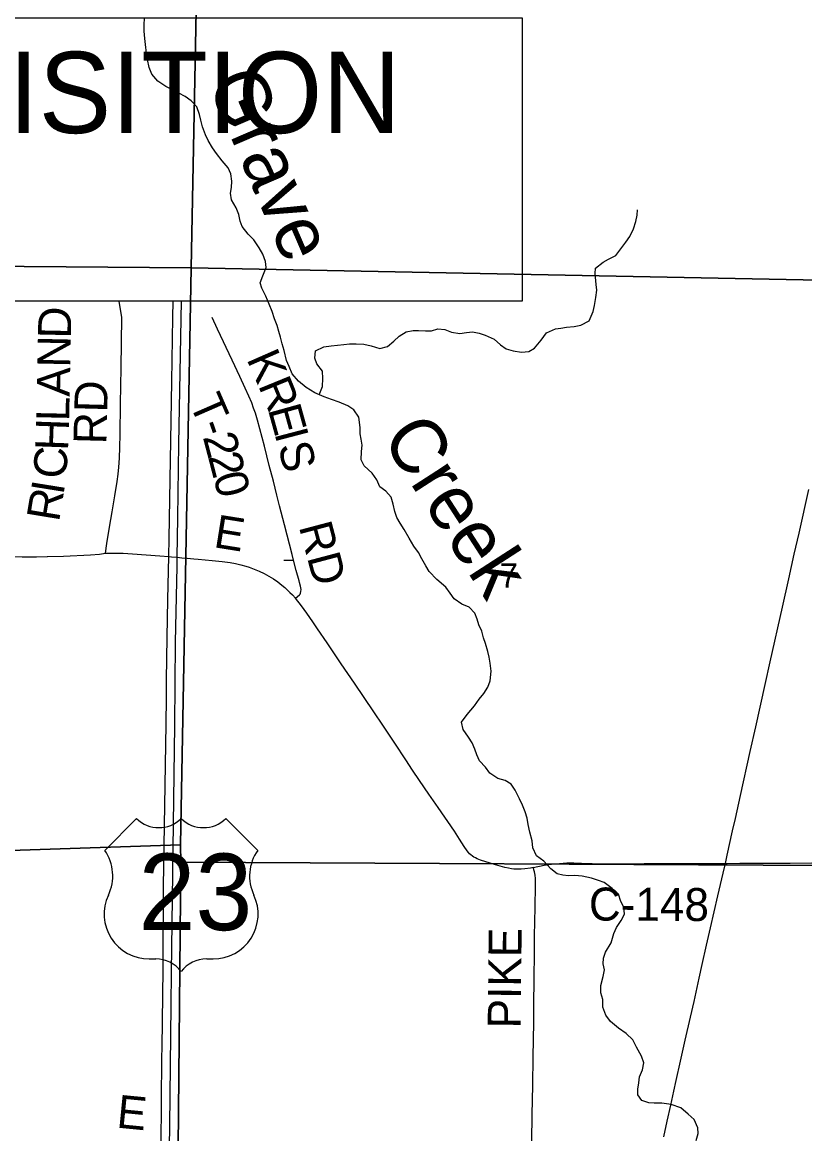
# Model space of a CAD drawing. Extents: x -97 to 34, y -21 to 22.
# Drawn here: x 8.293 to 9.642, y 14.954 to 16.869 of the extents above; entities that cross this region are included whole.
import ezdxf

# ---------------------------------------------------------------- set-up
doc = ezdxf.new("R2010")
doc.units = 0
for name, color, linetype in [('GM_X_County_Road', 7, 'Continuous'), ('GM_X_County_Road_Text', 7, 'Continuous'), ('GM_X_Minor_River', 7, 'Continuous'), ('GM_X_Minor_River_Text', 7, 'Continuous'), ('GM_X_Section', 7, 'Continuous'), ('GM_X_Section_Text', 7, 'Continuous'), ('GM_X_State_Route', 7, 'Continuous'), ('GM_X_Township_Road', 7, 'Continuous'), ('GM_X_Township_Road_Text', 7, 'Continuous'), ('GM_X_US_Location', 7, 'Continuous'), ('GM_X_US_Route', 7, 'Continuous'), ('GM_X_US_Shield', 7, 'Continuous'), ('SH_Text', 7, 'Continuous')]:
    doc.layers.add(name, color=color, linetype=linetype)

msp = doc.modelspace()

# ---------------------------------------------------------------- linework, layer by layer
at = {"layer": 'GM_X_County_Road'}
for points in [[(8.4647, 16.3607), (8.4598, 16.3891)], [(8.4365, 15.9545), (8.4388, 15.9715), (8.4434, 15.9997), (8.448, 16.0262), (8.4525, 16.0537), (8.4566, 16.0785), (8.4581, 16.0908), (8.4593, 16.1031), (8.4603, 16.1186), (8.4612, 16.1373), (8.4617, 16.159), (8.4623, 16.2119), (8.4627, 16.2431), (8.4633, 16.2742), (8.4647, 16.3607)], [(8.3356, 15.949), (8.3365, 15.949), (8.3642, 15.9495), (8.4105, 15.952), (8.4261, 15.9533), (8.4365, 15.9545)], [(8.4365, 15.9545), (8.4669, 15.9547), (8.483, 15.9538), (8.5302, 15.9504), (8.5455, 15.949), (8.5501, 15.9486)], [(7.6431, 15.9497), (7.6648, 15.9493), (7.699, 15.9492), (7.7487, 15.9488), (7.786, 15.9486), (7.814, 15.9485), (7.8668, 15.9481), (7.9134, 15.9483), (7.9507, 15.9485), (7.9849, 15.9486), (8.016, 15.9486), (8.0595, 15.9487), (8.1155, 15.9489), (8.1466, 15.9488), (8.1901, 15.9491), (8.2211, 15.9491), (8.2926, 15.9482), (8.3175, 15.9487), (8.3356, 15.949)], [(8.5501, 15.9486), (8.5597, 15.9477), (8.568, 15.947), (8.5769, 15.9462)], [(8.5769, 15.9462), (8.5888, 15.9451)], [(8.5888, 15.9451), (8.5959, 15.9445), (8.6205, 15.9421), (8.6372, 15.9404), (8.6513, 15.9384), (8.6604, 15.9368), (8.6694, 15.9349), (8.6784, 15.9325), (8.6842, 15.9307), (8.6929, 15.9274), (8.7014, 15.9238), (8.7097, 15.9197), (8.7178, 15.9152), (8.7257, 15.9104), (8.7333, 15.9051), (8.7406, 15.8995), (8.7453, 15.8955), (8.7544, 15.8871), (8.7589, 15.8828), (8.764, 15.8774)], [(8.8018, 15.8245), (8.7938, 15.8362), (8.7832, 15.8516), (8.7741, 15.8642), (8.764, 15.8774)], [(9.1738, 15.413), (9.1689, 15.4123), (9.1591, 15.411), (9.1529, 15.4104), (9.1466, 15.4101), (9.1434, 15.4102), (9.1403, 15.4104), (9.1363, 15.4108), (9.1309, 15.4118), (9.1248, 15.4133), (9.1128, 15.4167), (9.092, 15.4231), (9.0831, 15.4261), (9.0772, 15.4282), (9.0743, 15.4296), (9.0715, 15.431), (9.0689, 15.4327), (9.0662, 15.4348), (9.0639, 15.4369), (9.0619, 15.4392), (9.06, 15.4417), (9.0548, 15.4495), (9.0467, 15.4622), (9.0379, 15.4756), (9.0096, 15.5164), (8.9938, 15.5396), (8.9778, 15.5629), (8.9658, 15.581), (8.9539, 15.5988), (8.9351, 15.6273), (8.9142, 15.6583), (8.8987, 15.6816), (8.8655, 15.7306), (8.8428, 15.7641), (8.8183, 15.8001), (8.8018, 15.8245)], [(9.1738, 15.413), (9.1925, 15.4171), (9.2007, 15.4184), (9.2099, 15.4195), (9.2192, 15.4204), (9.2315, 15.421), (9.2439, 15.4212), (9.2572, 15.4208), (9.2755, 15.4199), (9.3018, 15.4194), (9.3216, 15.4196), (9.334, 15.4196), (9.365, 15.42), (9.3915, 15.4202), (9.4271, 15.42), (9.4426, 15.4199), (9.4955, 15.4202), (9.505, 15.4204)], [(9.505, 15.4204), (9.5079, 15.4204), (9.5296, 15.4205), (9.6166, 15.4206), (9.6538, 15.421), (9.7004, 15.4215), (9.7315, 15.4218), (9.8247, 15.4226), (9.862, 15.4227), (9.8993, 15.423), (9.9583, 15.4236), (10.0235, 15.4242), (10.0608, 15.4247), (10.0918, 15.4248), (10.1384, 15.4252), (10.2037, 15.4255), (10.2316, 15.4257), (10.272, 15.4256), (10.3031, 15.4254), (10.3404, 15.4254), (10.3515, 15.4255)], [(9.1709, 14.9143), (9.1712, 14.9413), (9.1719, 14.9878), (9.1728, 15.0375), (9.1735, 15.0871), (9.1745, 15.1461), (9.1748, 15.1802), (9.1752, 15.2174), (9.1758, 15.2702), (9.1761, 15.2919), (9.1767, 15.3229), (9.1769, 15.3415), (9.1778, 15.3849), (9.1776, 15.3942), (9.1772, 15.4003), (9.1767, 15.4031), (9.176, 15.406), (9.1738, 15.413)]]:
    msp.add_lwpolyline(points, dxfattribs=at)
at = {"layer": 'GM_X_Minor_River'}
for points in [[(8.6034, 16.689), (8.6008, 16.7008), (8.5982, 16.7106), (8.5937, 16.7236), (8.5838, 16.7338), (8.5736, 16.7414), (8.5627, 16.7475), (8.5509, 16.7533), (8.5403, 16.7586), (8.5267, 16.7681), (8.5162, 16.7799), (8.5117, 16.7917), (8.5087, 16.805), (8.5072, 16.8164), (8.5054, 16.8311), (8.5039, 16.8414), (8.5032, 16.8543), (8.5032, 16.8656), (8.5036, 16.8759)], [(9.1127, 15.5664), (9.0987, 15.5756), (9.0915, 15.5858), (9.081, 15.5972), (9.0765, 15.6075), (9.0731, 15.617), (9.0686, 15.628), (9.0622, 15.6378), (9.0531, 15.6508), (9.0501, 15.6637), (9.0597, 15.6769), (9.0722, 15.6916), (9.0806, 15.703), (9.0886, 15.7132), (9.0955, 15.7238), (9.0997, 15.7347), (9.1013, 15.7514), (9.0994, 15.7654), (9.0979, 15.7753), (9.0953, 15.7855), (9.0912, 15.7992), (9.0882, 15.8091), (9.0849, 15.8201), (9.08, 15.8311), (9.077, 15.8409), (9.0728, 15.8516), (9.063, 15.8615), (9.0505, 15.8668), (9.0373, 15.8759), (9.0305, 15.8858), (9.023, 15.8961), (9.0075, 15.9094), (8.9943, 15.9231), (8.9886, 15.933), (8.9819, 15.9448), (8.9762, 15.9558), (8.9679, 15.9668), (8.9596, 15.9805), (8.9514, 15.9957), (8.9442, 16.0063), (8.9385, 16.0162), (8.9352, 16.0264), (8.9322, 16.0389), (8.9288, 16.0511), (8.9194, 16.0613), (8.9092, 16.069), (8.9039, 16.0811), (8.896, 16.0925), (8.882, 16.1054), (8.8771, 16.1157), (8.8776, 16.1301), (8.8788, 16.1407), (8.8773, 16.1509), (8.8754, 16.1604), (8.8751, 16.1714), (8.8729, 16.1889), (8.8646, 16.2018), (8.854, 16.2083), (8.8389, 16.2148), (8.826, 16.2197), (8.8131, 16.2243), (8.7972, 16.2308), (8.7825, 16.24), (8.7693, 16.251), (8.7583, 16.2639), (8.7527, 16.2761), (8.7482, 16.2867), (8.7444, 16.3038), (8.7411, 16.3156), (8.7381, 16.3266), (8.7351, 16.3368), (8.7321, 16.3467), (8.7276, 16.3584), (8.7235, 16.3713), (8.7186, 16.3839), (8.7126, 16.3975), (8.7058, 16.4112), (8.7032, 16.4207), (8.7074, 16.4328), (8.7131, 16.4468), (8.712, 16.4574), (8.7075, 16.4699), (8.7011, 16.481), (8.6921, 16.4946), (8.6823, 16.5045), (8.6721, 16.5174), (8.6687, 16.5269), (8.6665, 16.5383), (8.6616, 16.5497), (8.6533, 16.5634), (8.6518, 16.5751), (8.6534, 16.585), (8.6542, 16.5956), (8.6523, 16.6081), (8.6478, 16.6187), (8.6377, 16.6305), (8.6278, 16.6431), (8.6207, 16.6529), (8.6131, 16.6655), (8.6086, 16.6754), (8.6034, 16.689)], [(8.8048, 16.2277), (8.8105, 16.2421), (8.8113, 16.2554), (8.8103, 16.2683), (8.8008, 16.2812), (8.7971, 16.2907), (8.7986, 16.3032), (8.8127, 16.3104), (8.8252, 16.3122), (8.8472, 16.3144), (8.8571, 16.3155), (8.8684, 16.3155), (8.8817, 16.3147), (8.8946, 16.312), (8.909, 16.3074), (8.9226, 16.3107), (8.9333, 16.3198), (8.9428, 16.3285), (8.9545, 16.336), (8.9667, 16.3382), (8.9762, 16.3386), (8.9879, 16.3378), (8.9985, 16.3377), (9.0095, 16.3411), (9.0216, 16.3399), (9.033, 16.3357), (9.047, 16.333), (9.0584, 16.3352), (9.069, 16.3363), (9.0808, 16.334), (9.091, 16.3302), (9.1061, 16.3233), (9.1174, 16.3138), (9.1273, 16.3069), (9.1394, 16.3035), (9.1534, 16.3011), (9.1663, 16.3022), (9.1758, 16.3079), (9.1876, 16.3219), (9.1964, 16.3343), (9.2119, 16.3411), (9.2214, 16.3426), (9.2313, 16.3441), (9.2442, 16.3452), (9.2559, 16.3474), (9.2704, 16.3549), (9.2772, 16.3712), (9.2792, 16.3814), (9.2815, 16.3951), (9.2834, 16.4076), (9.2823, 16.4178), (9.2805, 16.4364), (9.2813, 16.4458), (9.2942, 16.456), (9.3037, 16.4613), (9.3159, 16.4677), (9.3334, 16.4904), (9.3403, 16.5002), (9.3464, 16.5138), (9.3506, 16.5263), (9.3529, 16.5369), (9.3537, 16.5464)], [(9.4544, 14.9429), (9.4579, 14.955), (9.4576, 14.9649), (9.4512, 14.9789), (9.441, 14.9884), (9.4281, 14.9994), (9.4115, 15.0052), (9.3952, 15.0071), (9.3823, 15.0072), (9.3728, 15.0076), (9.3607, 15.0118), (9.3539, 15.0213), (9.354, 15.0316), (9.3559, 15.0422), (9.3571, 15.0528), (9.362, 15.0649), (9.3644, 15.0766), (9.3602, 15.0884), (9.3516, 15.1036), (9.3456, 15.1161), (9.3339, 15.1275), (9.3206, 15.1366), (9.307, 15.1477), (9.2987, 15.1587), (9.2939, 15.1727), (9.2939, 15.1856), (9.2905, 15.1974), (9.2902, 15.2099), (9.2944, 15.2254), (9.2964, 15.2368), (9.2941, 15.247), (9.2949, 15.2569), (9.2984, 15.2671), (9.3079, 15.2834), (9.3125, 15.2996), (9.3175, 15.3099), (9.3255, 15.322), (9.3309, 15.3329), (9.3298, 15.3451), (9.3245, 15.3549), (9.3208, 15.3671), (9.3098, 15.3773), (9.2962, 15.3872), (9.2864, 15.3911), (9.2739, 15.3949), (9.2583, 15.3984), (9.2455, 15.3996), (9.2345, 15.3988), (9.225, 15.4), (9.2152, 15.4023), (9.2042, 15.4107), (9.1921, 15.424), (9.1796, 15.4335), (9.1729, 15.4472), (9.1718, 15.4593), (9.168, 15.4741), (9.1647, 15.4874), (9.1632, 15.498), (9.1598, 15.5094), (9.1553, 15.5208), (9.1501, 15.5318), (9.1426, 15.5466), (9.1354, 15.5569), (9.1256, 15.5633), (9.1127, 15.5664)]]:
    msp.add_lwpolyline(points, dxfattribs=at)
at = {"layer": 'GM_X_Section'}
for points in [[(8.6036, 17.4499), (8.5841, 16.4464), (7.5768, 16.4545), (7.5928, 17.458)], [(9.712, 17.4373), (9.6974, 16.4247), (8.5841, 16.4464), (8.6036, 17.4499)], [(7.5768, 16.4545), (8.5841, 16.4464), (8.5658, 15.452), (8.0641, 15.4358), (7.5679, 15.4518)], [(8.5841, 16.4464), (9.6974, 16.4247), (9.6813, 15.4167), (8.566, 15.4224), (8.5658, 15.452)], [(7.5679, 15.4518), (8.0641, 15.4358), (8.5658, 15.452), (8.566, 15.4224), (8.5572, 14.4394), (7.5552, 14.4456)], [(8.566, 15.4224), (9.6813, 15.4167), (9.6648, 14.4117), (8.5567, 14.4125), (8.5572, 14.4394)]]:
    msp.add_lwpolyline(points, close=True, dxfattribs=at)
at = {"layer": 'GM_X_State_Route'}
msp.add_lwpolyline([(9.3987, 14.949), (9.4047, 14.9763), (9.4109, 15.0035), (9.4163, 15.0278), (9.4201, 15.046), (9.4275, 15.0794), (9.4357, 15.1157), (9.4447, 15.1551), (9.4509, 15.1824), (9.4597, 15.2223), (9.4652, 15.2462), (9.4725, 15.2795), (9.4795, 15.3095), (9.4917, 15.3644), (9.501, 15.4037), (9.505, 15.4204), (9.5079, 15.4342), (9.5174, 15.4766), (9.5223, 15.4978), (9.5311, 15.5372), (9.5479, 15.613), (9.5572, 15.6556), (9.5734, 15.7284), (9.5822, 15.7678), (9.6033, 15.862), (9.6142, 15.9103), (9.6237, 15.9529), (9.6321, 15.9894), (9.6488, 16.0644)], dxfattribs=at)
at = {"layer": 'GM_X_Township_Road'}
for points in [[(8.7606, 15.9425), (8.7582, 15.9522), (8.7448, 16.0033), (8.7362, 16.0365), (8.7318, 16.0546), (8.7257, 16.0787), (8.7186, 16.1058), (8.7102, 16.1389), (8.7024, 16.1691), (8.6983, 16.1841), (8.6947, 16.196), (8.6917, 16.2048), (8.6884, 16.2135), (8.6836, 16.225), (8.6772, 16.2392), (8.668, 16.2589), (8.655, 16.287), (8.6294, 16.3405), (8.62, 16.3607)], [(8.7438, 15.9425), (8.7568, 15.9425), (8.7606, 15.9425)], [(8.764, 15.8774), (8.7708, 15.8831), (8.7718, 15.8844), (8.7724, 15.8858), (8.7733, 15.8888), (8.7734, 15.8919), (8.773, 15.8949), (8.7723, 15.8979), (8.7706, 15.904), (8.7701, 15.9069), (8.7651, 15.925), (8.7606, 15.9425)]]:
    msp.add_lwpolyline(points, dxfattribs=at)
at = {"layer": 'GM_X_US_Route'}
for points in [[(8.541, 14.0177), (8.5415, 14.1387), (8.542, 14.319), (8.5432, 14.5303), (8.5454, 14.754), (8.5469, 14.932), (8.5472, 14.9684), (8.5494, 15.1758), (8.55, 15.2325), (8.5558, 15.6582), (8.5573, 15.8011), (8.5578, 15.8278), (8.5597, 15.9316), (8.5597, 15.9477), (8.5611, 16.0155), (8.5629, 16.1429), (8.5673, 16.3891)], [(8.5527, 16.3607), (8.5532, 16.3891)], [(8.5268, 14.0177), (8.5268, 14.0508), (8.5274, 14.2434), (8.5279, 14.4423), (8.5292, 14.5541), (8.5301, 14.6784), (8.5321, 14.8027), (8.5324, 14.9053), (8.5326, 14.9339), (8.5336, 15.0855), (8.5338, 15.1038), (8.5355, 15.2377), (8.5364, 15.3807), (8.5409, 15.6603), (8.5414, 15.7055), (8.5417, 15.7365), (8.5425, 15.8094), (8.5438, 15.8747), (8.5455, 15.949), (8.5463, 15.9803), (8.5507, 16.2506), (8.5527, 16.3607)]]:
    msp.add_lwpolyline(points, dxfattribs=at)
at = {"layer": 'GM_X_US_Shield'}
for p, q in [((8.4899, 15.4976), (8.435, 15.4427)), ((8.6987, 15.4427), (8.6437, 15.4976)), ((8.5119, 15.2559), (8.5229, 15.2559)), ((8.6108, 15.2559), (8.6218, 15.2559))]:
    msp.add_line(p, q, dxfattribs=at)
for centre, radius, start, end in [((8.5284, 15.5368), 0.0549, 225.573, 314.427), ((8.6053, 15.5368), 0.0549, 225.573, 314.427), ((8.372, 15.3986), 0.0769, 334.5471, 35.0009), ((8.7617, 15.3986), 0.0769, 144.9991, 205.4529), ((8.511, 15.3328), 0.0769, 154.8319, 270.6383), ((8.6226, 15.3328), 0.0769, 269.3617, 25.1681), ((8.5229, 15.201), 0.0549, 36.8699, 90), ((8.6108, 15.201), 0.0549, 90, 143.1301)]:
    msp.add_arc(centre, radius, start, end, dxfattribs=at)
at = {"layer": 'SH_Text'}
msp.add_lwpolyline([(7.0407, 16.8772), (9.1549, 16.8772), (9.1549, 16.3891), (7.0407, 16.3891)], close=True, dxfattribs=at)

# ---------------------------------------------------------------- texts
at = {"layer": 'GM_X_County_Road_Text'}
for s, height, rotation, p in [('D', 0.0568, 88.7723, (8.3766, 16.3241)), ('N', 0.0568, 88.7723, (8.3755, 16.2741)), ('A', 0.0568, 88.7723, (8.3745, 16.2241)), ('RD', 0.05682, 88.5116, (8.4378, 16.1419)), ('L', 0.0568, 88.7791, (8.3736, 16.1816)), ('H', 0.0568, 87.9339, (8.3717, 16.1307)), ('C', 0.0568, 85.5794, (8.368, 16.0817)), ('I', 0.0568, 80.8824, (8.3637, 16.0536)), ('R', 0.0568, 80.6461, (8.3561, 16.0073)), ('E', 0.0568, 350.9456, (8.6212, 15.9653)), ('C-148', 0.05682, 359.7241, (9.2696, 15.3219)), ('PIKE', 0.05682, 89.3877, (9.152, 15.1358)), ('E', 0.0568, 354.4003, (8.4542, 14.9653))]:
    msp.add_text(s, height=height, rotation=rotation, dxfattribs=at).set_placement(p)
at = {"layer": 'GM_X_Minor_River_Text'}
for s, height, rotation, p in [('Grave', 0.09471, 293.3298, (8.6111, 16.766)), ('Creek', 0.0947, 302.8291, (8.9106, 16.1539))]:
    msp.add_text(s, height=height, rotation=rotation, dxfattribs=at).set_placement(p)
at = {"layer": 'GM_X_Section_Text'}
msp.add_text('7', height=0.0419, rotation=0, dxfattribs=at).set_placement((9.116, 15.8954))
at = {"layer": 'GM_X_Township_Road_Text'}
for s, height, rotation, p in [('K', 0.0568, 293.6965, (8.6789, 16.2896)), ('R', 0.0568, 292.2305, (8.6989, 16.2442)), ('T', 0.0568, 293.5931, (8.58, 16.214)), ('E', 0.0568, 285.5322, (8.716, 16.2027)), ('2', 0.0568, 284.7595, (8.6039, 16.1552)), ('-', 0.0568, 289.2175, (8.5966, 16.1761)), ('I', 0.0568, 284.6705, (8.7273, 16.1619)), ('S', 0.0568, 284.6263, (8.7332, 16.1394)), ('2', 0.0568, 284.555, (8.6128, 16.1214)), ('0', 0.0568, 284.5184, (8.6216, 16.0875)), ('RD', 0.05682, 284.8671, (8.7694, 16.0008))]:
    msp.add_text(s, height=height, rotation=rotation, dxfattribs=at).set_placement(p)
at = {"layer": 'GM_X_US_Location'}
for s in ['0', '/']:
    msp.add_text(s, height=0.000189, dxfattribs=at).set_placement((8.5668, 16.3551))
msp.add_text('23', height=0.000189, rotation=0, dxfattribs=at).set_placement((8.5277, 16.3159))
at = {"layer": 'GM_X_US_Shield'}
msp.add_text('23', height=0.13184, dxfattribs=at).set_placement((8.4934, 15.3053))
at = {"layer": 'SH_Text'}
msp.add_text('BEGIN ACQUISITION', height=0.14, dxfattribs=at).set_placement((7.0938, 16.6785))

doc.saveas('drawing.dxf')
